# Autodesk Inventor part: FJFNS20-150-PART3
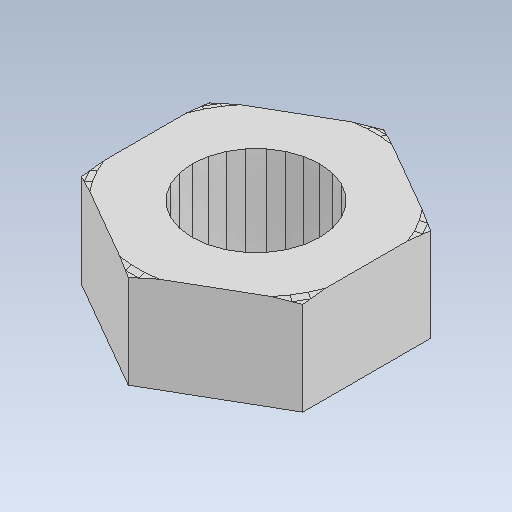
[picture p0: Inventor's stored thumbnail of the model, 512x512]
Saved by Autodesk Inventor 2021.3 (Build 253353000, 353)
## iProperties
Created: 2022-02
Part Number: FJFNS20-150-PART3
Material: 一般
Document SubType Name: Modeling
Designer: kengo
Density: 1 g/cm^3
Appearance: 既定
Author: kengo
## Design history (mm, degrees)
feature "FJFNS20-150-PART3"
node "ソリッド1"
